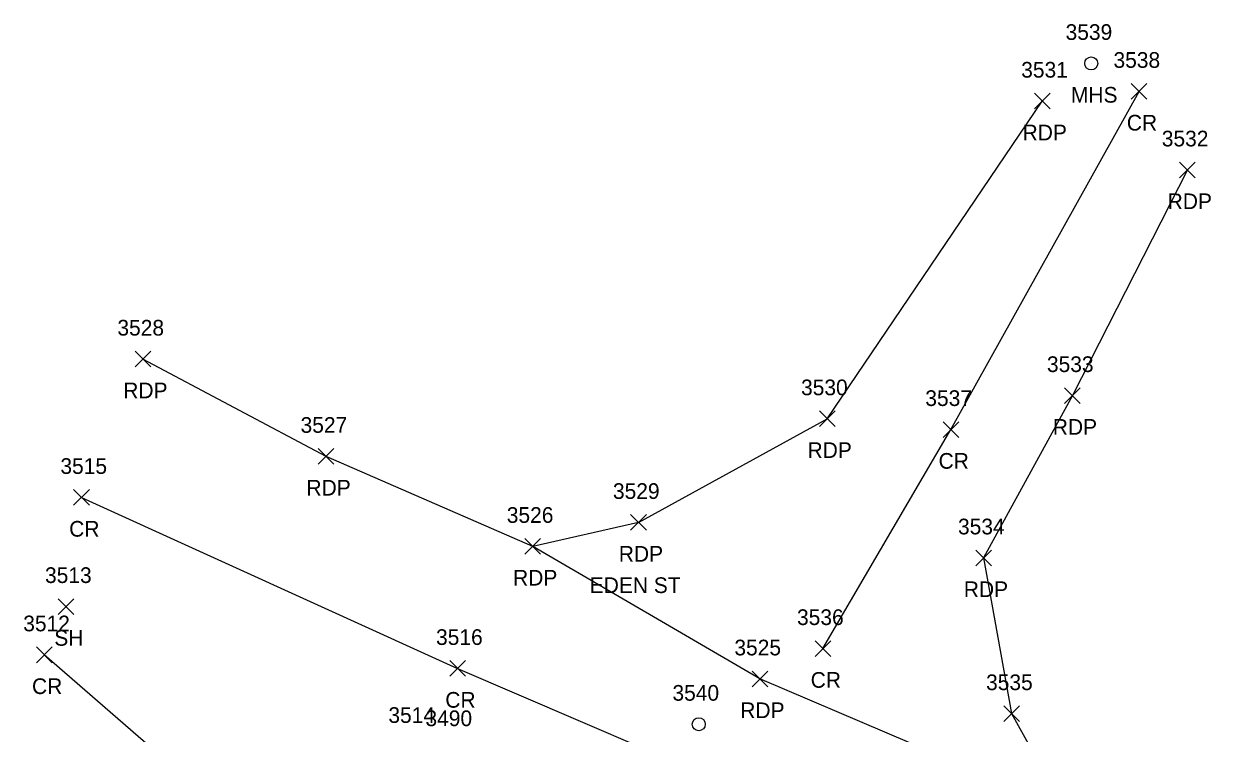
# Model space of a CAD drawing. Extents: x 1609623 to 1616187, y 756677 to 762826.
# Drawn here: x 1610476 to 1610629, y 762735 to 762825.6 of the extents above; entities that cross this region are included whole.
import ezdxf

# ---------------------------------------------------------------- set-up
doc = ezdxf.new("R2010")
doc.units = 0
for name, color, linetype in [('L_A', 7, 'Continuous'), ('L_I', 7, 'Continuous'), ('L_TIC', 7, 'Continuous'), ('P_A', 7, 'Continuous'), ('P_C', 7, 'Continuous'), ('P_I', 7, 'Continuous'), ('P_TIC', 7, 'Continuous'), ('PET', 7, 'Continuous'), ('PRC', 7, 'Continuous'), ('U_A', 7, 'Continuous'), ('U_I', 7, 'Continuous'), ('USMH', 7, 'Continuous')]:
    doc.layers.add(name, color=color, linetype=linetype)

msp = doc.modelspace()

# ---------------------------------------------------------------- linework, layer by layer
at = {"layer": 'L_TIC'}
for points in [[(1610480.33, 762750.28), (1610482.33, 762752.28)], [(1610482.33, 762750.28), (1610480.33, 762752.28)]]:
    msp.add_lwpolyline(points, dxfattribs=at)
at = {"layer": 'P_TIC'}
for points in [[(1610617.17, 762815.97), (1610619.17, 762817.97)], [(1610619.17, 762815.97), (1610617.17, 762817.97)], [(1610604.83, 762814.72), (1610606.83, 762816.72)], [(1610606.83, 762814.72), (1610604.83, 762816.72)], [(1610623.33, 762805.95), (1610625.33, 762807.95)], [(1610625.33, 762805.95), (1610623.33, 762807.95)], [(1610490.13, 762781.83), (1610492.13, 762783.83)], [(1610492.13, 762781.83), (1610490.13, 762783.83)], [(1610608.68, 762777.18), (1610610.68, 762779.18)], [(1610610.68, 762777.18), (1610608.68, 762779.18)], [(1610577.4, 762774.22), (1610579.4, 762776.22)], [(1610579.4, 762774.22), (1610577.4, 762776.22)], [(1610593.17, 762772.85), (1610595.17, 762774.85)], [(1610595.17, 762772.85), (1610593.17, 762774.85)], [(1610513.49, 762769.43), (1610515.49, 762771.43)], [(1610515.49, 762769.43), (1610513.49, 762771.43)], [(1610482.29, 762764.19), (1610484.29, 762766.19)], [(1610484.29, 762764.19), (1610482.29, 762766.19)], [(1610553.33, 762761), (1610555.33, 762763)], [(1610555.33, 762761), (1610553.33, 762763)], [(1610539.85, 762757.95), (1610541.85, 762759.95)], [(1610541.85, 762757.95), (1610539.85, 762759.95)], [(1610597.34, 762756.48), (1610599.34, 762758.48)], [(1610599.34, 762756.48), (1610597.34, 762758.48)], [(1610576.86, 762744.92), (1610578.86, 762746.92)], [(1610578.86, 762744.92), (1610576.86, 762746.92)], [(1610477.55, 762744.12), (1610479.55, 762746.12)], [(1610479.55, 762744.12), (1610477.55, 762746.12)], [(1610530.26, 762742.38), (1610532.26, 762744.38)], [(1610532.26, 762742.38), (1610530.26, 762744.38)], [(1610568.82, 762741.05), (1610570.82, 762743.05)], [(1610570.82, 762741.05), (1610568.82, 762743.05)], [(1610600.92, 762736.62), (1610602.92, 762738.62)], [(1610602.92, 762736.62), (1610600.92, 762738.62)]]:
    msp.add_lwpolyline(points, dxfattribs=at)
at = {"layer": 'PET'}
for points in [[(1610554.33, 762762), (1610578.4, 762775.22), (1610605.83, 762815.72)], [(1610624.33, 762806.95), (1610609.68, 762778.18), (1610598.34, 762757.48), (1610601.92, 762737.62)], [(1610726.73, 762732.18), (1610650.15, 762718.32), (1610608.66, 762725.5), (1610569.82, 762742.05), (1610540.85, 762758.95), (1610514.49, 762770.43), (1610491.13, 762782.83)], [(1610554.33, 762762), (1610540.85, 762758.95)], [(1610601.92, 762737.62), (1610608.66, 762725.5)]]:
    msp.add_lwpolyline(points, dxfattribs=at)
at = {"layer": 'PRC'}
for points in [[(1610577.86, 762745.92), (1610594.17, 762773.85), (1610618.17, 762816.97)], [(1610483.29, 762765.19), (1610531.26, 762743.38), (1610570.67, 762726.44), (1610610.26, 762712.27), (1610655.05, 762707.17), (1610689.94, 762710.36), (1610729.5, 762721.48)], [(1610521.41, 762702.68), (1610502.51, 762724.29), (1610478.55, 762745.12)]]:
    msp.add_lwpolyline(points, dxfattribs=at)
at = {"layer": 'USMH'}
for p, q in [((1610612.07, 762820.53), (1610612.07, 762820.53)), ((1610612.9, 762820.53), (1610612.9, 762820.53)), ((1610562.01, 762736.27), (1610562.01, 762736.27)), ((1610562.84, 762736.27), (1610562.84, 762736.27))]:
    msp.add_line(p, q, dxfattribs=at)
for centre in [(1610612.07, 762820.53), (1610562.01, 762736.27)]:
    msp.add_circle(centre, 0.833, dxfattribs=at)

# ---------------------------------------------------------------- texts
at = {"layer": 'L_A'}
msp.add_text('SH', height=2, dxfattribs=at).set_placement((1610479.82, 762746.28))
at = {"layer": 'L_I'}
for s, p in [('3513', (1610478.64, 762754.28)), ('3514', (1610522.43, 762736.44))]:
    msp.add_text(s, height=2, dxfattribs=at).set_placement(p)
at = {"layer": 'P_A'}
for s, p in [('RDP', (1610603.32, 762810.72)), ('CR', (1610616.61, 762811.97)), ('RDP', (1610621.82, 762801.95)), ('RDP', (1610488.62, 762777.83)), ('RDP', (1610607.17, 762773.18)), ('RDP', (1610575.89, 762770.22)), ('CR', (1610592.6, 762768.85)), ('RDP', (1610511.98, 762765.43)), ('CR', (1610481.72, 762760.19)), ('RDP', (1610551.82, 762757)), ('RDP', (1610538.33, 762753.95)), ('RDP', (1610595.82, 762752.48)), ('CR', (1610476.98, 762740.12)), ('CR', (1610576.29, 762740.92)), ('CR', (1610529.69, 762738.38)), ('RDP', (1610567.31, 762737.05))]:
    msp.add_text(s, height=2, dxfattribs=at).set_placement(p)
at = {"layer": 'P_C'}
msp.add_text('EDEN ST', height=2, dxfattribs=at).set_placement((1610548.11, 762753))
at = {"layer": 'P_I'}
for s, p in [('3538', (1610614.91, 762819.97)), ('3531', (1610603.14, 762818.72)), ('3532', (1610621.07, 762809.95)), ('3528', (1610487.87, 762785.83)), ('3533', (1610606.42, 762781.18)), ('3530', (1610575.06, 762778.22)), ('3537', (1610590.91, 762776.85)), ('3527', (1610511.23, 762773.43)), ('3515', (1610480.6, 762768.19)), ('3529', (1610551.07, 762765)), ('3526', (1610537.53, 762761.95)), ('3534', (1610595.08, 762760.48)), ('3512', (1610475.86, 762748.12)), ('3536', (1610574.55, 762748.92)), ('3516', (1610528.51, 762746.38)), ('3525', (1610566.56, 762745.05)), ('3535', (1610598.66, 762740.62)), ('3490', (1610527.16, 762736.03))]:
    msp.add_text(s, height=2, dxfattribs=at).set_placement(p)
at = {"layer": 'U_A'}
msp.add_text('MHS', height=2, dxfattribs=at).set_placement((1610609.48, 762815.53))
at = {"layer": 'U_I'}
for s, p in [('3539', (1610608.8, 762823.53)), ('3540', (1610558.66, 762739.27))]:
    msp.add_text(s, height=2, dxfattribs=at).set_placement(p)

doc.saveas('drawing.dxf')
